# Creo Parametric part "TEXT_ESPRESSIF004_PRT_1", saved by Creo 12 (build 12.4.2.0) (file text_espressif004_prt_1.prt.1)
Units: Custom; MM, KILOGRAM, SECS

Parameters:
  PTC_WM_ITERATION = "0"
  PTC_WM_VERSION = "-.0"
  PTC_WM_LIFECYCLE_STATE = "In Work"
  PTC_WM_LIFECYCLE = "MO_CADDocument"
  PTC_WM_CREATED_BY = "Maximilian Roepper (Z0017RMS: MO)"
  PTC_WM_CREATED_ON = "18-Sep-26 11:36:42 AM"
  PTC_WM_MODIFIED_BY = "Maximilian Roepper (Z0017RMS: MO)"
  PTC_WM_MODIFIED_ON = "18-Sep-26 11:36:46 AM"
  PDMLINKNUMBER = "PDM000071454884"
  PTC_WM_NAME = "text_espressif004_prt_1.prt"
  PTC_WM_NUMBER = "PDM000071454884"

Other parameters: WEIGHT, WEIGHT_FACTOR, WEIGHT_ADD, _MASS_TEMP, _DIFF_TEMP, MC_ERRORS, SUPPLIER

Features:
  1. coordinate system
  2. datum plane "PRT_YZ"
  3. datum plane "PRT_XY"
  4. datum plane "PRT_XZ"
  5. coordinate system
  6. datum axis
  7. datum axis
  8. datum axis
  9. coordinate system
  10. imported feature
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
Other named items: PRT, SIEMENS_MO, DRW_VIEW_ORG, PRT_X, PRT_Y, PRT_Z, CS0, ROUGH_GROB

Layers: 00_STD_CSYS-KSYS, 01_STD_PLANES-EBENEN, 02_STD_AXES-ACHSEN, 03_STD_CSYS-KSYS, 24_IMPORT_FEAT-IMPORT_KE

Surfaces: 14 plane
